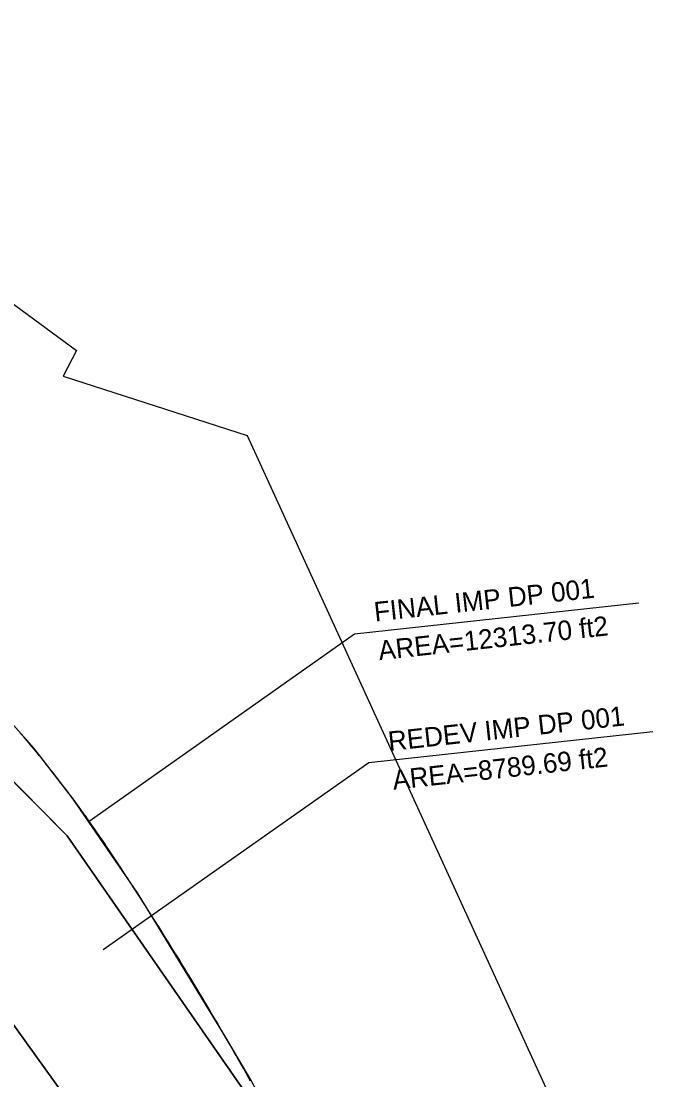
# Model space of a CAD drawing. Extents: x 1509538 to 1510847, y 401283 to 402022.
# Drawn here: x 1509708.7 to 1509799.5, y 401866.7 to 402018.9 of the extents above; entities that cross this region are included whole.
import ezdxf

# ---------------------------------------------------------------- set-up
doc = ezdxf.new("R2010")
doc.units = 0
for name, color, linetype in [('LDEFAULT_P', 7, 'Continuous'), ('Level 2', 7, 'Continuous'), ('Level 24', 7, 'Continuous'), ('Level 3', 7, 'Continuous'), ('Level 5', 7, 'Continuous'), ('Level 8', 7, 'Continuous')]:
    doc.layers.add(name, color=color, linetype=linetype)

msp = doc.modelspace()

# ---------------------------------------------------------------- linework, layer by layer
at = {"layer": 'LDEFAULT_P'}
for points in [[(1509718.48, 401903.86), (1509756.64, 401930.77), (1509797.48, 401935.22)], [(1509720.5, 401885.38), (1509758.66, 401912.29), (1509799.49, 401916.74)]]:
    msp.add_lwpolyline(points, dxfattribs=at)
at = {"layer": 'Level 2'}
for p, q in [((1509715.31, 401901.72), (1509679, 401938.37)), ((1509715.31, 401901.72), (1509679, 401938.37)), ((1509745.32, 401858.52), (1509715.31, 401901.72))]:
    msp.add_line(p, q, dxfattribs=at)
for points in [[(1509797.62, 401715.81), (1509783.05, 401763.87), (1509766.29, 401811.16), (1509745.32, 401858.52), (1509715.31, 401901.72)], [(1509690.27, 401895.46), (1509701.64, 401882.87), (1509726.68, 401848.01), (1509747.74, 401803.4), (1509763.81, 401758.01), (1509775.46, 401713.07), (1509786.05, 401661.7), (1509787.8, 401644.85), (1509788.16, 401621.99), (1509786.62, 401596.26), (1509780.1, 401566.45), (1509768.35, 401517.81), (1509766.66, 401509.48)], [(1509690.27, 401895.46), (1509701.64, 401882.87), (1509726.68, 401848.01), (1509747.74, 401803.4)]]:
    msp.add_lwpolyline(points, dxfattribs=at)
at = {"layer": 'Level 24'}
msp.add_lwpolyline([(1509697.15, 401864.06), (1509686.29, 401879.63), (1509675.11, 401894.56), (1509657.75, 401913.27), (1509630.7, 401928.99), (1509603.66, 401944.71), (1509584.86, 401956.59), (1509560.78, 401974.8), (1509538.38, 401997.91), (1509540.54, 401998.4), (1509554.21, 402018.88), (1509601.36, 402010.05), (1509610.5, 402004.57), (1509626.83, 401997.75), (1509642.89, 401994.81), (1509700.83, 401983.19), (1509716.67, 401971.54), (1509714.74, 401967.81), (1509741.2, 401959.3), (1509785.47, 401862.6)], dxfattribs=at)
at = {"layer": 'Level 3'}
msp.add_line((1509679, 401938.37), (1509715.31, 401901.72), dxfattribs=at)
for points in [[(1509741.69, 401866.48), (1509741.34, 401867.09), (1509741, 401867.7), (1509740.66, 401868.31), (1509740.31, 401868.92), (1509740.24, 401869.05), (1509740.04, 401869.39), (1509739.96, 401869.53), (1509739.61, 401870.14), (1509739.27, 401870.74), (1509738.92, 401871.35), (1509738.57, 401871.96), (1509738.22, 401872.56), (1509737.93, 401873.05), (1509737.86, 401873.17), (1509737.51, 401873.77), (1509737.47, 401873.85), (1509737.16, 401874.38), (1509736.81, 401874.98), (1509736.45, 401875.58), (1509736.09, 401876.18), (1509735.74, 401876.79), (1509735.6, 401877.03), (1509735.38, 401877.39), (1509735.02, 401877.99), (1509734.85, 401878.28), (1509734.66, 401878.59), (1509734.3, 401879.19), (1509733.94, 401879.79), (1509733.58, 401880.39), (1509733.22, 401880.99), (1509732.86, 401881.59), (1509732.49, 401882.18), (1509732.18, 401882.69), (1509732.13, 401882.78), (1509731.76, 401883.38), (1509731.4, 401883.98), (1509731.03, 401884.57), (1509730.81, 401884.92), (1509730.66, 401885.17), (1509730.29, 401885.76), (1509729.92, 401886.36), (1509729.55, 401886.95), (1509729.48, 401887.07), (1509729.18, 401887.54), (1509728.81, 401888.14), (1509728.44, 401888.73), (1509728.37, 401888.83), (1509728.06, 401889.32), (1509727.69, 401889.91), (1509727.31, 401890.5), (1509726.94, 401891.09), (1509726.72, 401891.43), (1509726.56, 401891.68), (1509726.18, 401892.27), (1509725.89, 401892.72), (1509725.8, 401892.86), (1509725.43, 401893.45), (1509725.05, 401894.04), (1509724.66, 401894.62), (1509724.28, 401895.21), (1509723.93, 401895.75), (1509723.9, 401895.8), (1509723.52, 401896.38), (1509723.38, 401896.59), (1509723.13, 401896.97), (1509722.75, 401897.55), (1509722.36, 401898.14), (1509721.98, 401898.72), (1509721.59, 401899.3), (1509721.2, 401899.88), (1509721.09, 401900.05), (1509720.83, 401900.44), (1509720.81, 401900.47), (1509720.4, 401901.09), (1509719.97, 401901.71), (1509719.55, 401902.32), (1509719.25, 401902.76), (1509719.13, 401902.94), (1509718.7, 401903.55), (1509718.27, 401904.16), (1509717.99, 401904.55), (1509717.83, 401904.77), (1509717.64, 401905.04), (1509717.4, 401905.38), (1509716.96, 401905.98), (1509716.52, 401906.59), (1509716.07, 401907.18), (1509715.99, 401907.3), (1509715.62, 401907.78), (1509715.17, 401908.38), (1509714.72, 401908.97), (1509714.29, 401909.53), (1509714.27, 401909.57), (1509713.81, 401910.16), (1509713.35, 401910.75), (1509712.88, 401911.33), (1509712.56, 401911.73), (1509712.42, 401911.92), (1509711.95, 401912.5), (1509711.48, 401913.08), (1509711.31, 401913.29), (1509711, 401913.66), (1509710.8, 401913.9), (1509710.53, 401914.23), (1509710.05, 401914.81), (1509709.56, 401915.38), (1509709.08, 401915.95), (1509708.99, 401916.05), (1509708.59, 401916.51)], [(1509715.31, 401901.72), (1509745.32, 401858.52), (1509766.29, 401811.16), (1509783.05, 401763.87), (1509797.62, 401715.81)], [(1509747.74, 401803.4), (1509726.68, 401848.01), (1509701.64, 401882.87), (1509690.27, 401895.46)]]:
    msp.add_lwpolyline(points, dxfattribs=at)
at = {"layer": 'Level 5'}
for p, q in [((1509710.56, 401914.31), (1509702.51, 401923.27)), ((1509716.11, 401907.14), (1509710.56, 401914.31)), ((1509725.54, 401893.38), (1509716.11, 401907.14)), ((1509738.13, 401872.76), (1509725.54, 401893.38)), ((1509741.72, 401866.65), (1509738.13, 401872.76)), ((1509754.95, 401841.45), (1509741.72, 401866.65))]:
    msp.add_line(p, q, dxfattribs=at)
at = {"layer": 'Level 8'}
for p, q in [((1509679, 401938.37), (1509715.31, 401901.72)), ((1509715.31, 401901.72), (1509745.32, 401858.52))]:
    msp.add_line(p, q, dxfattribs=at)
msp.add_lwpolyline([(1509747.74, 401803.4), (1509726.68, 401848.01), (1509701.64, 401882.87), (1509690.27, 401895.46)], dxfattribs=at)

# ---------------------------------------------------------------- texts
at = {"layer": 'LDEFAULT_P'}
for s, p in [('FINAL IMP DP 001', (1509759.58, 401932.54)), ('AREA=12313.70 ft2', (1509760.19, 401926.98)), ('REDEV IMP DP 001', (1509761.61, 401913.92)), ('AREA=8789.69 ft2', (1509762.22, 401908.35))]:
    msp.add_text(s, height=2.8, rotation=6.2219, dxfattribs=at).set_placement(p)

doc.saveas('drawing.dxf')
